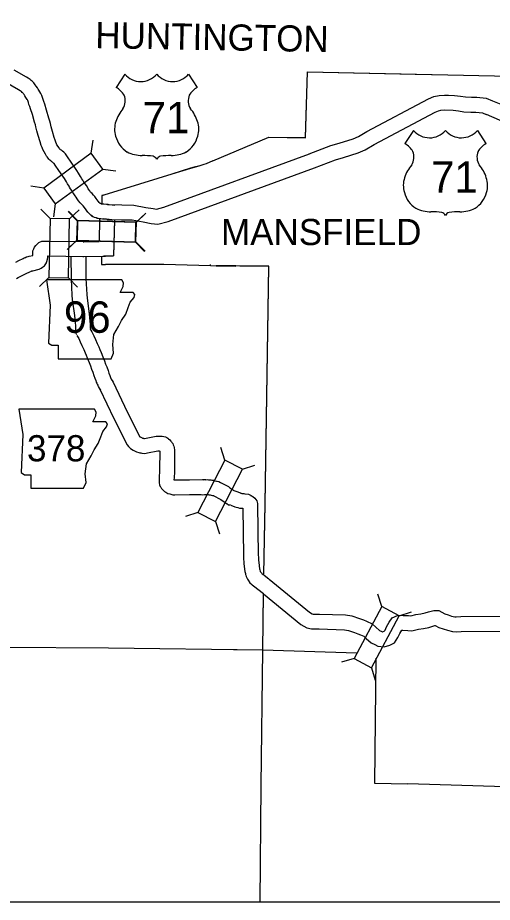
# Model space of a CAD drawing. Extents: x 1370567 to 1373900, y 377514 to 379648.
# Drawn here: x 1371027.9 to 1371123.6, y 378768.1 to 378946.6 of the extents above; entities that cross this region are included whole.
import ezdxf

# ---------------------------------------------------------------- set-up
doc = ezdxf.new("R2010")
doc.units = 0
doc.layers.add('Default', color=7, linetype='Continuous')
doc.layers.add('Survey Symbols', color=7, linetype='Continuous')

msp = doc.modelspace()

# ---------------------------------------------------------------- linework, layer by layer
at = {"layer": 'Default'}
for p, q in [((1371049.51, 378935.18), (1371047.78, 378932.5)), ((1371062.38, 378935.18), (1371064.11, 378932.5)), ((1371107.75, 378923.82), (1371106.02, 378921.15)), ((1371120.62, 378923.82), (1371122.35, 378921.15)), ((1371042.73, 378919.22), (1371043.13, 378921.83)), ((1371045.08, 378916.03), (1371047.69, 378915.63)), ((1371033.16, 378912.18), (1371030.55, 378912.58)), ((1371035.5, 378908.99), (1371035.11, 378906.38)), ((1371034.43, 378906.02), (1371032.59, 378907.92)), ((1371039.9, 378905.56), (1371038.08, 378907.47)), ((1371039.99, 378905.61), (1371038.17, 378907.52)), ((1371038.39, 378905.95), (1371040.29, 378907.79)), ((1371051.77, 378905.25), (1371053.69, 378907.07)), ((1371051.87, 378905.3), (1371053.78, 378907.12)), ((1371039.8, 378901.6), (1371037.88, 378899.78)), ((1371039.89, 378901.65), (1371037.98, 378899.83)), ((1371039.8, 378901.6), (1371039.65, 378901.46)), ((1371051.67, 378901.29), (1371053.49, 378899.38)), ((1371051.77, 378901.35), (1371053.59, 378899.43)), ((1371034.21, 378894.15), (1371032.31, 378892.31)), ((1371038.17, 378894.07), (1371040, 378892.17)), ((1371069.7, 378857.3), (1371068.89, 378859.82)), ((1371073.22, 378855.49), (1371075.74, 378856.3)), ((1371075.33, 378849.97), (1371075.77, 378849.59)), ((1371064.27, 378846.74), (1371061.75, 378845.93)), ((1371067.79, 378844.93), (1371068.6, 378842.41)), ((1371101.34, 378827.74), (1371100.57, 378830.26)), ((1371104.83, 378825.87), (1371107.36, 378826.64)), ((1371095.75, 378817.25), (1371093.22, 378816.49)), ((1371099.24, 378815.39), (1371100.01, 378812.86))]:
    msp.add_line(p, q, dxfattribs=at)
for points in [[(1371067.27, 378917.67), (1371078.54, 378922.47), (1371085.98, 378922.37), (1371086.39, 378935.64), (1371127.23, 378934.77), (1371127.44, 378948.17), (1371147.75, 378947.75), (1371148.1, 378954.32), (1371154.59, 378954.28), (1371154.68, 378960.65), (1371181.85, 378960.51), (1371182.04, 378973.93), (1371209.34, 378973.69), (1371210.17, 379020.3)], [(1371114.67, 378935.02), (1371127.23, 378934.75), (1371127.44, 378948.15), (1371147.75, 378947.73), (1371148.1, 378954.3), (1371154.59, 378954.26), (1371154.68, 378960.64), (1371181.85, 378960.5), (1371182.04, 378973.92), (1371209.33, 378973.68)], [(1371047.5, 378908.7), (1371045.29, 378908.97), (1371045.13, 378908.95), (1371044.8, 378908.98), (1371044.59, 378909.06), (1371044.56, 378909.08), (1371044.49, 378909.16), (1371044.41, 378909.22), (1371044.37, 378909.26), (1371043.76, 378910.08), (1371043.47, 378910.45), (1371043.23, 378910.76), (1371042.91, 378911.07), (1371042.68, 378911.31), (1371042.6, 378911.39), (1371042.47, 378911.64), (1371042.14, 378912.06), (1371042.05, 378912.21), (1371041.76, 378912.7), (1371041.53, 378913.01), (1371041.4, 378913.22), (1371041.23, 378913.45), (1371041.13, 378913.58), (1371041.04, 378913.77), (1371040.87, 378914.07), (1371040.57, 378914.55), (1371040.41, 378914.88), (1371040.2, 378915.16), (1371039.82, 378915.76), (1371038.67, 378917.4), (1371037.96, 378918.51), (1371037.55, 378919.07), (1371037.19, 378919.42), (1371036.96, 378919.62), (1371036.75, 378919.8), (1371036.55, 378919.93), (1371036.46, 378920), (1371036.45, 378920.01), (1371036.4, 378920.06), (1371036.36, 378920.12), (1371036.26, 378920.28), (1371036.19, 378920.37), (1371036.05, 378920.6), (1371035.84, 378920.94), (1371035.75, 378921.13), (1371035.63, 378921.48), (1371035.46, 378921.84), (1371035.29, 378922.39), (1371034.92, 378923.59), (1371034.67, 378924.52), (1371034.5, 378925.21), (1371034.39, 378925.71), (1371034.21, 378926.3), (1371033.74, 378927.93), (1371033.36, 378929.09), (1371033.19, 378929.67), (1371033.02, 378930.09), (1371032.91, 378930.43), (1371032.75, 378930.89), (1371032.6, 378931.28), (1371032.4, 378931.62), (1371032.21, 378931.91), (1371032.06, 378932.13), (1371031.89, 378932.39), (1371031.67, 378932.76), (1371031.44, 378933.05), (1371031.2, 378933.39), (1371030.83, 378933.74), (1371030.64, 378933.9), (1371030.4, 378934.12), (1371030.04, 378934.33), (1371029.71, 378934.57), (1371027.23, 378935.95)], [(1371067.26, 378917.66), (1371078.54, 378922.45), (1371085.98, 378922.35), (1371086.39, 378935.62), (1371108.06, 378935.16), (1371114.67, 378935.02)], [(1371047.44, 378905.68), (1371045.26, 378905.95), (1371045, 378905.92), (1371044.7, 378905.98), (1371044.44, 378906), (1371043.92, 378906.08), (1371043.74, 378906.17), (1371043.67, 378906.19), (1371043.42, 378906.25), (1371042.94, 378906.49), (1371042.68, 378906.75), (1371042.59, 378906.81), (1371042.48, 378906.92), (1371042.34, 378907.03), (1371042.06, 378907.35), (1371041.36, 378908.27), (1371041.1, 378908.61), (1371040.99, 378908.76), (1371040.78, 378908.96), (1371040.53, 378909.22), (1371040.15, 378909.61), (1371039.94, 378910.01), (1371039.68, 378910.34), (1371039.49, 378910.65), (1371039.26, 378911.04), (1371039.06, 378911.31), (1371038.91, 378911.54), (1371038.8, 378911.7), (1371038.57, 378912.01), (1371038.38, 378912.38), (1371038.29, 378912.55), (1371037.96, 378913.07), (1371037.84, 378913.3), (1371037.73, 378913.46), (1371037.32, 378914.09), (1371036.18, 378915.73), (1371035.48, 378916.81), (1371035.26, 378917.11), (1371035.14, 378917.23), (1371035.01, 378917.35), (1371034.96, 378917.39), (1371034.8, 378917.49), (1371034.6, 378917.65), (1371034.4, 378917.81), (1371034.19, 378918.04), (1371034.03, 378918.21), (1371033.86, 378918.46), (1371033.74, 378918.64), (1371033.66, 378918.76), (1371033.5, 378919.02), (1371033.23, 378919.47), (1371032.98, 378919.94), (1371032.84, 378920.37), (1371032.66, 378920.75), (1371032.42, 378921.5), (1371032.04, 378922.77), (1371031.77, 378923.76), (1371031.58, 378924.51), (1371031.48, 378924.96), (1371031.33, 378925.46), (1371030.87, 378927.05), (1371030.49, 378928.2), (1371030.36, 378928.67), (1371030.19, 378929.08), (1371030.07, 378929.48), (1371029.93, 378929.86), (1371029.89, 378929.97), (1371029.85, 378930.03), (1371029.72, 378930.24), (1371029.57, 378930.46), (1371029.34, 378930.81), (1371029.19, 378931.06), (1371029.04, 378931.25), (1371028.92, 378931.42), (1371028.84, 378931.49), (1371028.67, 378931.64), (1371028.61, 378931.69), (1371028.39, 378931.82), (1371028.09, 378932.04), (1371025.53, 378933.46)], [(1371086.71, 378919.06), (1371091.06, 378920.76), (1371092.75, 378921.22), (1371095.57, 378922.14), (1371096.65, 378922.58), (1371098.35, 378923.59), (1371110.79, 378930.16), (1371111.87, 378930.69), (1371112.9, 378930.86), (1371113.98, 378930.94), (1371114.75, 378930.91)], [(1371114.82, 378930.91), (1371115.99, 378930.87), (1371117.19, 378930.73), (1371118.22, 378930.59), (1371119.41, 378930.52), (1371120.48, 378930.52), (1371122.38, 378930.3), (1371123.68, 378929.77), (1371125.99, 378928.84)], [(1371087.8, 378916.27), (1371092, 378917.91), (1371093.6, 378918.34), (1371096.6, 378919.32), (1371097.98, 378919.88), (1371099.82, 378920.97), (1371112.14, 378927.49), (1371112.79, 378927.8), (1371113.26, 378927.88), (1371114.04, 378927.94), (1371115.76, 378927.88), (1371116.81, 378927.76), (1371117.92, 378927.6), (1371119.32, 378927.52), (1371120.31, 378927.52), (1371121.63, 378927.36), (1371122.37, 378927.06)], [(1371122.39, 378927.1), (1371127.62, 378924.8)], [(1371046.01, 378908.86), (1371048.93, 378908.79), (1371051.35, 378908.76), (1371053.73, 378908.29), (1371055.21, 378908.03), (1371055.94, 378907.96), (1371057.37, 378908.33), (1371086.74, 378919.08)], [(1371067.27, 378917.67), (1371065.93, 378917.1), (1371065.44, 378916.96), (1371064.66, 378916.69), (1371063.53, 378916.37), (1371062.78, 378916.17), (1371059.01, 378915.01), (1371049.66, 378912.11), (1371045.51, 378910.82)], [(1371067.26, 378917.66), (1371065.93, 378917.08), (1371065.44, 378916.94), (1371064.66, 378916.67), (1371063.53, 378916.35), (1371062.77, 378916.15), (1371059.01, 378914.99), (1371049.66, 378912.09), (1371045.51, 378910.8)], [(1371045.95, 378905.86), (1371048.88, 378905.79), (1371051.03, 378905.76), (1371053.19, 378905.34), (1371054.81, 378905.06), (1371056.18, 378904.93), (1371058.26, 378905.47), (1371087.77, 378916.26)], [(1371045.51, 378910.8), (1371044.88, 378910.64), (1371044.87, 378909.02)], [(1371045.51, 378910.82), (1371044.88, 378910.66), (1371044.88, 378910.46)], [(1371046.16, 378908.84), (1371045.29, 378908.95), (1371045.13, 378908.94), (1371044.8, 378908.97), (1371044.59, 378909.04), (1371044.56, 378909.06), (1371044.49, 378909.14), (1371044.41, 378909.2), (1371044.37, 378909.24), (1371044.21, 378909.46)], [(1371045.8, 378905.87), (1371045.26, 378905.93), (1371045, 378905.91), (1371044.7, 378905.96), (1371044.44, 378905.99), (1371043.92, 378906.07), (1371043.74, 378906.16), (1371043.67, 378906.17), (1371043.42, 378906.23), (1371042.94, 378906.47), (1371042.68, 378906.73), (1371042.59, 378906.8), (1371042.48, 378906.9), (1371042.34, 378907.02), (1371042.06, 378907.33), (1371041.81, 378907.65)], [(1371044.44, 378906.02), (1371044.33, 378901.44)], [(1371044.44, 378905.97), (1371044.33, 378901.43)], [(1371047.44, 378905.85), (1371047.25, 378898.49)], [(1371047.44, 378905.71), (1371047.25, 378898.52)], [(1371029.4, 378898.15), (1371029.49, 378898.19), (1371029.7, 378898.28), (1371030.01, 378898.36), (1371030.23, 378898.42), (1371030.97, 378898.6), (1371030.97, 378899.49), (1371031.14, 378899.93), (1371031.27, 378900.23), (1371031.54, 378900.59), (1371031.81, 378900.86), (1371031.88, 378900.92), (1371032.18, 378901.19), (1371032.75, 378901.48), (1371034.48, 378901.49), (1371041.26, 378901.37), (1371044.33, 378901.44)], [(1371041.1, 378901.36), (1371041.26, 378901.35), (1371044.33, 378901.43)], [(1371027.53, 378897.23), (1371028.17, 378897.55), (1371028.99, 378897.95), (1371029.22, 378898.11), (1371029.57, 378898.21)], [(1371030.54, 378895.38), (1371030.65, 378895.42), (1371030.69, 378895.44), (1371030.76, 378895.46), (1371030.95, 378895.5), (1371032.27, 378895.82), (1371032.68, 378896.01), (1371032.95, 378896.19), (1371033.31, 378896.48), (1371033.7, 378897.12), (1371033.72, 378897.15), (1371033.82, 378897.35), (1371033.95, 378897.81), (1371033.97, 378898.16), (1371033.97, 378898.36), (1371033.97, 378898.5), (1371041.27, 378898.37), (1371045.07, 378898.46), (1371045.31, 378898.47), (1371045.37, 378898.48), (1371045.52, 378898.48), (1371045.59, 378898.49), (1371047.25, 378898.5)], [(1371038.66, 378898.45), (1371038.68, 378893.83), (1371038.86, 378890.57), (1371038.91, 378889.71), (1371039.34, 378886.47), (1371039.5, 378885.02), (1371039.54, 378884.48), (1371039.57, 378883.9), (1371039.58, 378883.65), (1371039.59, 378883.59), (1371039.59, 378883.41), (1371039.61, 378883.17), (1371039.67, 378882.91), (1371039.78, 378882.63)], [(1371041.05, 378898.36), (1371041.27, 378898.35), (1371045.07, 378898.44), (1371045.31, 378898.46), (1371045.37, 378898.46), (1371045.52, 378898.46), (1371045.59, 378898.47), (1371047.25, 378898.49)], [(1371041.66, 378898.37), (1371041.68, 378893.92), (1371041.86, 378890.74), (1371041.9, 378889.99), (1371042.32, 378886.83), (1371042.49, 378885.3), (1371042.54, 378884.66), (1371042.56, 378884.08), (1371042.58, 378883.78), (1371042.58, 378883.68)], [(1371044.84, 378898.45), (1371044.83, 378896.77), (1371045.64, 378896.77)], [(1371044.84, 378898.43), (1371044.83, 378896.76), (1371045.64, 378896.76)], [(1371066.78, 378896.52), (1371057.39, 378896.75), (1371045.64, 378896.77)], [(1371066.78, 378896.5), (1371057.39, 378896.74), (1371045.64, 378896.76)], [(1371077.56, 378834.21), (1371077.85, 378848.44), (1371078.54, 378896.4), (1371066.78, 378896.52), (1371066.79, 378896.76)], [(1371077.56, 378834.21), (1371077.85, 378848.42), (1371078.54, 378896.38), (1371066.78, 378896.5), (1371066.79, 378896.74)], [(1371067.92, 378896.49), (1371071.9, 378896.45)], [(1371071.9, 378896.45), (1371071.9, 378896.49), (1371068.08, 378896.49), (1371067.92, 378896.49)], [(1371027.66, 378893.95), (1371028.01, 378894.11), (1371028.3, 378894.26), (1371028.56, 378894.4), (1371028.84, 378894.53), (1371029.5, 378894.86), (1371030.5, 378895.35), (1371030.5, 378895.36)], [(1371042.49, 378883.88), (1371042.87, 378883.2), (1371043.07, 378882.8), (1371043.27, 378882.38), (1371043.61, 378881.62), (1371043.97, 378880.83), (1371044.27, 378880.18), (1371044.51, 378879.63), (1371044.74, 378879.02), (1371045.11, 378878.1), (1371045.4, 378877.35), (1371045.63, 378876.68), (1371045.87, 378876.08), (1371046.13, 378875.34), (1371046.3, 378874.85), (1371046.49, 378874.35), (1371046.56, 378874.15), (1371046.64, 378873.96), (1371046.73, 378873.75), (1371046.79, 378873.6), (1371046.87, 378873.44)], [(1371039.86, 378882.43), (1371040.22, 378881.8), (1371040.37, 378881.49), (1371040.54, 378881.13), (1371040.87, 378880.39), (1371041.24, 378879.58), (1371041.53, 378878.95), (1371041.73, 378878.49), (1371041.95, 378877.94), (1371042.31, 378877), (1371042.59, 378876.3), (1371042.82, 378875.64), (1371043.05, 378875.03), (1371043.3, 378874.35), (1371043.48, 378873.82), (1371043.67, 378873.33), (1371043.77, 378873.04), (1371043.88, 378872.79), (1371043.96, 378872.59), (1371044.05, 378872.38), (1371044.12, 378872.22)], [(1371046.83, 378873.51), (1371046.88, 378873.41), (1371046.95, 378873.32), (1371047.16, 378873)], [(1371044.16, 378872.15), (1371044.33, 378871.81), (1371044.51, 378871.58), (1371044.61, 378871.42)], [(1371044.5, 378871.61), (1371047.33, 378865.69), (1371050, 378860.39), (1371050.27, 378860.02), (1371050.66, 378859.63), (1371051.2, 378859.32), (1371051.48, 378859.18), (1371051.89, 378858.96), (1371052.36, 378858.83), (1371052.57, 378858.78), (1371052.74, 378858.74), (1371052.98, 378858.68), (1371053.56, 378858.63), (1371054.11, 378858.74), (1371056.18, 378859.13), (1371056.38, 378859.14), (1371056.47, 378859.15), (1371056.54, 378859.14), (1371056.54, 378859.11), (1371056.55, 378859.07), (1371056.55, 378859.05), (1371056.55, 378858.95), (1371056.52, 378855.51), (1371056.53, 378855.32), (1371056.52, 378855.09), (1371056.44, 378853.82), (1371056.42, 378852.99), (1371056.47, 378852.67), (1371056.52, 378852.32), (1371056.68, 378851.98), (1371056.77, 378851.81), (1371056.93, 378851.54), (1371057.16, 378851.29), (1371057.33, 378851.14), (1371057.53, 378850.97), (1371057.79, 378850.81), (1371058.19, 378850.57), (1371058.61, 378850.45), (1371058.81, 378850.39), (1371059.01, 378850.33), (1371059.22, 378850.31), (1371059.36, 378850.3), (1371059.59, 378850.28), (1371062.54, 378850.33)], [(1371047.16, 378873), (1371050.02, 378867.01), (1371052.55, 378862.01), (1371052.61, 378861.97), (1371052.85, 378861.85), (1371053.02, 378861.76), (1371053.11, 378861.74), (1371053.3, 378861.69), (1371053.37, 378861.67), (1371053.44, 378861.67), (1371053.52, 378861.68), (1371055.84, 378862.12), (1371056.2, 378862.13), (1371056.4, 378862.15), (1371056.82, 378862.14), (1371057.07, 378862.1), (1371057.36, 378862.07), (1371057.69, 378861.96), (1371057.97, 378861.82), (1371058.16, 378861.7), (1371058.27, 378861.62), (1371058.3, 378861.59), (1371058.6, 378861.39), (1371058.78, 378861.14), (1371058.86, 378861.05), (1371058.91, 378860.99), (1371059.01, 378860.87), (1371059.2, 378860.61), (1371059.29, 378860.36), (1371059.41, 378860.11), (1371059.46, 378859.83), (1371059.49, 378859.67), (1371059.53, 378859.43), (1371059.55, 378859.19), (1371059.55, 378858.95), (1371059.52, 378855.57), (1371059.54, 378855.32), (1371059.52, 378854.91), (1371059.44, 378853.7), (1371059.43, 378853.33), (1371059.46, 378853.33), (1371059.59, 378853.29), (1371059.59, 378853.29), (1371059.66, 378853.28), (1371062.58, 378853.33)], [(1371062.58, 378853.33), (1371065.14, 378853.36), (1371065.31, 378853.34), (1371065.39, 378853.35), (1371065.77, 378853.35), (1371065.85, 378853.34), (1371066.1, 378853.37), (1371066.38, 378853.32), (1371066.48, 378853.31), (1371066.72, 378853.3), (1371066.89, 378853.28), (1371067.07, 378853.27), (1371067.42, 378853.21), (1371067.65, 378853.14), (1371067.75, 378853.12), (1371068, 378853.07), (1371068.15, 378853.04), (1371068.45, 378852.95), (1371068.83, 378852.76), (1371070.4, 378851.95), (1371070.69, 378851.71), (1371071.25, 378851.33), (1371071.41, 378851.22), (1371071.43, 378851.21), (1371071.52, 378851.17), (1371071.94, 378851)], [(1371062.54, 378850.33), (1371064.93, 378850.36), (1371065.24, 378850.31), (1371065.57, 378850.35), (1371065.61, 378850.35), (1371065.84, 378850.32), (1371065.96, 378850.33), (1371066.35, 378850.32), (1371066.47, 378850.31), (1371066.62, 378850.29), (1371066.7, 378850.29), (1371066.95, 378850.21), (1371067.2, 378850.17), (1371067.37, 378850.13), (1371067.46, 378850.09), (1371068.72, 378849.44), (1371068.88, 378849.31), (1371069.56, 378848.85), (1371069.75, 378848.72), (1371070.01, 378848.56), (1371070.1, 378848.52), (1371070.45, 378848.28), (1371070.77, 378848.24), (1371070.86, 378848.21)], [(1371071.94, 378851), (1371072.82, 378850.67), (1371072.86, 378850.65), (1371073.01, 378850.62), (1371073.14, 378850.58), (1371073.34, 378850.57), (1371073.55, 378850.52), (1371073.7, 378850.51), (1371074.43, 378850.42), (1371074.84, 378850.2), (1371074.87, 378850.18), (1371074.98, 378850.15), (1371075.22, 378850.03), (1371075.33, 378849.97)], [(1371070.89, 378848.19), (1371071.73, 378847.87), (1371071.99, 378847.77), (1371072.28, 378847.71), (1371072.63, 378847.61), (1371073.31, 378847.56)], [(1371075.77, 378849.59), (1371076.16, 378849.1), (1371076.27, 378848.5), (1371076.27, 378848.42), (1371076.3, 378848.24), (1371076.44, 378838.14), (1371076.46, 378837.72), (1371076.47, 378837.43), (1371076.5, 378837.02), (1371076.53, 378836.71), (1371076.7, 378835.31), (1371076.72, 378835.24), (1371076.76, 378835.13), (1371076.82, 378834.87), (1371076.83, 378834.83), (1371076.86, 378834.77), (1371077.05, 378834.52), (1371077.16, 378834.41), (1371077.25, 378834.35), (1371077.56, 378834.11)], [(1371073.31, 378847.56), (1371073.44, 378838.03), (1371073.47, 378837.62), (1371073.47, 378837.31), (1371073.51, 378836.77), (1371073.54, 378836.38), (1371073.74, 378834.81), (1371073.83, 378834.4), (1371073.89, 378834.23), (1371073.93, 378834.09), (1371074, 378833.83), (1371074.12, 378833.55), (1371074.23, 378833.28), (1371074.39, 378833.03), (1371074.71, 378832.54), (1371075.1, 378832.23), (1371075.21, 378832.12), (1371075.44, 378831.95), (1371077.46, 378830.39)], [(1371077.59, 378834.06), (1371078.58, 378833.3)], [(1371078.62, 378833.27), (1371086.73, 378826.6), (1371087.32, 378826.28), (1371087.53, 378826.23), (1371088.75, 378826.22), (1371094.05, 378826.04), (1371095.32, 378825.85), (1371096.85, 378825.35), (1371097.63, 378825.03), (1371098.24, 378824.8), (1371099.37, 378824.25), (1371100.13, 378823.59), (1371100.91, 378822.93), (1371101.34, 378822.7), (1371101.43, 378822.66), (1371101.51, 378822.65), (1371101.82, 378822.75), (1371101.84, 378822.76), (1371101.99, 378822.98), (1371102.31, 378823.67), (1371102.83, 378824.57), (1371103.45, 378825.47), (1371104.51, 378825.95), (1371105.32, 378825.97), (1371105.68, 378825.96), (1371106.73, 378825.91), (1371107.17, 378825.89), (1371108.23, 378826.1), (1371109.19, 378826.26), (1371110.11, 378826.46), (1371110.79, 378826.65), (1371111.32, 378826.82), (1371111.85, 378826.92), (1371112.82, 378826.93), (1371114.08, 378826.28), (1371114.71, 378826.05), (1371115.43, 378825.83), (1371116.04, 378825.67), (1371116.37, 378825.65), (1371117.25, 378825.72), (1371126.78, 378825.78)], [(1371077.04, 378791.66), (1371077.34, 378818.96), (1371077.49, 378830.37)], [(1371077.5, 378830.31), (1371085.03, 378824.11), (1371086.25, 378823.44), (1371087.2, 378823.23), (1371088.68, 378823.22), (1371093.79, 378823.04), (1371094.63, 378822.92), (1371095.81, 378822.53), (1371096.53, 378822.24), (1371097.05, 378822.04), (1371097.7, 378821.73), (1371098.18, 378821.32), (1371099.22, 378820.43), (1371099.94, 378820.05), (1371100.53, 378819.74), (1371101.83, 378819.59), (1371102.97, 378819.97), (1371103.91, 378820.43), (1371104.61, 378821.52), (1371104.97, 378822.28), (1371105.37, 378822.97), (1371105.37, 378822.97), (1371105.57, 378822.97), (1371106.57, 378822.92), (1371107.38, 378822.87), (1371108.77, 378823.15), (1371109.76, 378823.32), (1371110.84, 378823.54), (1371111.65, 378823.78), (1371112.06, 378823.9), (1371112.12, 378823.92), (1371112.88, 378823.53), (1371113.75, 378823.21), (1371114.61, 378822.95), (1371115.57, 378822.7), (1371116.39, 378822.65), (1371117.37, 378822.72), (1371126.89, 378822.79)], [(1371077.04, 378791.64), (1371077.33, 378818.94), (1371077.49, 378830.25)], [(1370918.14, 378794.66), (1370956.1, 378794.22), (1370971.56, 378794), (1370998.12, 378793.7), (1370998.19, 378806.82), (1371025.01, 378806.31), (1371025.06, 378819.55), (1371046.21, 378819.39)], [(1371046.21, 378819.39), (1371077.32, 378819.01)], [(1371071.43, 378819.06), (1371077.32, 378818.99)], [(1371077.32, 378818.99), (1371096.23, 378818.43)], [(1371100.11, 378817.32), (1371099.84, 378792.09), (1371106.57, 378791.95)], [(1371076.79, 378768.06), (1371077.04, 378791.66)], [(1371076.79, 378768.06), (1371077.04, 378791.64)], [(1371231.15, 378790.18), (1371204.96, 378790.59), (1371178.94, 378790.98), (1371152.65, 378791.25), (1371126.25, 378791.39), (1371106.57, 378791.95)]]:
    msp.add_lwpolyline(points, dxfattribs=at)
for points in [[(1371042.73, 378919.22), (1371033.16, 378912.18), (1371035.5, 378908.99), (1371045.08, 378916.03)], [(1371038.17, 378894.07), (1371038.39, 378905.95), (1371034.43, 378906.02), (1371034.21, 378894.15)], [(1371039.8, 378901.6), (1371051.67, 378901.29), (1371051.77, 378905.25), (1371039.9, 378905.56)], [(1371051.87, 378905.3), (1371039.99, 378905.61), (1371039.89, 378901.65), (1371051.77, 378901.35)], [(1371033.72, 378893.64), (1371034.48, 378888.57), (1371034.14, 378880.87), (1371034.82, 378880.45), (1371036.08, 378880.45), (1371036.08, 378877.74), (1371046.74, 378877.74), (1371047.25, 378878.84), (1371047.08, 378880.62), (1371047.33, 378882.65), (1371048.27, 378884.25), (1371048.86, 378885.44), (1371049.7, 378886.71), (1371050.21, 378888.06), (1371050.63, 378889.16), (1371051.39, 378890.09), (1371051.56, 378890.68), (1371051.23, 378891.11), (1371048.6, 378891.11), (1371049.2, 378892.29), (1371049.28, 378893.05), (1371048.93, 378893.64)], [(1371028.17, 378867.55), (1371028.93, 378862.48), (1371028.59, 378854.78), (1371029.27, 378854.35), (1371030.54, 378854.35), (1371030.54, 378851.65), (1371041.2, 378851.65), (1371041.71, 378852.75), (1371041.54, 378854.52), (1371041.79, 378856.55), (1371042.72, 378858.16), (1371043.31, 378859.35), (1371044.16, 378860.61), (1371044.67, 378861.97), (1371045.09, 378863.07), (1371045.85, 378864), (1371046.02, 378864.59), (1371045.68, 378865.01), (1371043.06, 378865.01), (1371043.65, 378866.2), (1371043.74, 378866.96), (1371043.38, 378867.54)], [(1371069.7, 378857.3), (1371064.27, 378846.74), (1371067.79, 378844.93), (1371073.22, 378855.49)], [(1371099.24, 378815.39), (1371104.83, 378825.87), (1371101.34, 378827.74), (1371095.75, 378817.25)]]:
    msp.add_lwpolyline(points, close=True, dxfattribs=at)
for centre, radius, start, end in [((1371052.74, 378937.89), 4.21, 220.075, 319.6701), ((1371059.16, 378937.89), 4.21, 220.3299, 319.925), ((1371045.52, 378928.61), 4.5, 30.7809, 59.9883), ((1371066.37, 378928.61), 4.5, 120.0117, 149.2191), ((1371046.51, 378929.8), 3.08, 328.8105, 21.2108), ((1371065.39, 378929.8), 3.08, 158.7892, 211.1895), ((1371054.57, 378923.48), 7.19, 138.9565, 162.6913), ((1371057.32, 378923.48), 7.19, 17.3087, 41.0435), ((1371052.2, 378924.07), 4.75, 160.9576, 197.3819), ((1371059.7, 378924.07), 4.75, 342.6181, 19.0424), ((1371110.97, 378926.54), 4.21, 220.075, 319.6701), ((1371117.39, 378926.54), 4.21, 220.3299, 319.925), ((1371052.97, 378924.08), 5.5, 195.1074, 237.1312), ((1371058.92, 378924.08), 5.5, 302.8688, 344.8926), ((1371103.75, 378917.26), 4.5, 30.7809, 59.9883), ((1371104.74, 378918.45), 3.08, 328.8105, 21.2108), ((1371123.62, 378918.45), 3.08, 158.7892, 211.1895), ((1371124.61, 378917.26), 4.5, 120.0117, 149.2191), ((1371053.07, 378925.82), 7.06, 244.0771, 269.5779), ((1371053.24, 378905.82), 12.93, 81.1942, 90.9539), ((1371054.85, 378917.42), 1.24, 28.0342, 72.9864), ((1371057.04, 378917.42), 1.24, 107.0136, 151.9658), ((1371058.66, 378905.82), 12.93, 89.0461, 98.8058), ((1371058.82, 378925.82), 7.06, 270.4221, 295.9229), ((1371112.81, 378912.13), 7.19, 138.9565, 162.6913), ((1371115.56, 378912.13), 7.19, 17.3087, 41.0435), ((1371110.43, 378912.72), 4.75, 160.9576, 197.3819), ((1371117.93, 378912.72), 4.75, 342.6181, 19.0424), ((1371111.2, 378912.73), 5.5, 195.1074, 237.1312), ((1371117.16, 378912.73), 5.5, 302.8688, 344.8926), ((1371111.31, 378914.46), 7.06, 244.0771, 269.5779), ((1371111.47, 378894.47), 12.93, 81.1942, 90.9539), ((1371113.09, 378906.07), 1.24, 28.0342, 72.9864), ((1371115.28, 378906.07), 1.24, 107.0136, 151.9658), ((1371116.89, 378894.47), 12.93, 89.0461, 98.8058), ((1371117.06, 378914.46), 7.06, 270.4221, 295.9229)]:
    msp.add_arc(centre, radius, start, end, dxfattribs=at)
at = {"layer": 'Survey Symbols'}
msp.add_lwpolyline([(1370727.27, 379552.54), (1371456.67, 379552.54), (1371456.67, 378768.06), (1370727.27, 378768.06)], close=True, dxfattribs=at)
msp.add_lwpolyline([(1370727.27, 379552.54), (1371456.67, 379552.54), (1371456.67, 378768.06), (1370727.27, 378768.06)], close=True, dxfattribs=at)
msp.add_lwpolyline([(1370727.27, 379552.54), (1371456.67, 379552.54), (1371456.67, 378768.06), (1370727.27, 378768.06)], close=True, dxfattribs=at)
msp.add_lwpolyline([(1370727.27, 379552.54), (1371456.67, 379552.54), (1371456.67, 378768.06), (1370727.27, 378768.06)], close=True, dxfattribs=at)
msp.add_lwpolyline([(1370727.27, 379552.54), (1371456.67, 379552.54), (1371456.67, 378768.06), (1370727.27, 378768.06)], close=True, dxfattribs=at)
msp.add_lwpolyline([(1370727.27, 379552.54), (1371456.67, 379552.54), (1371456.67, 378768.06), (1370727.27, 378768.06)], close=True, dxfattribs=at)

# ---------------------------------------------------------------- texts
at = {"layer": 'Default'}
msp.add_text('HUNTINGTON', height=5.28, rotation=359, dxfattribs=at).set_placement((1371043.53, 378940.43))
for s, height, p in [('71', 6.336, (1371053.12, 378923.25)), ('71', 6.336, (1371111.28, 378911.25)), ('MANSFIELD', 5.28, (1371068.92, 378900.68)), ('96', 6.336, (1371037.24, 378882.98)), ('378', 5.28, (1371029.79, 378857.04))]:
    msp.add_text(s, height=height, dxfattribs=at).set_placement(p)

doc.saveas('drawing.dxf')
